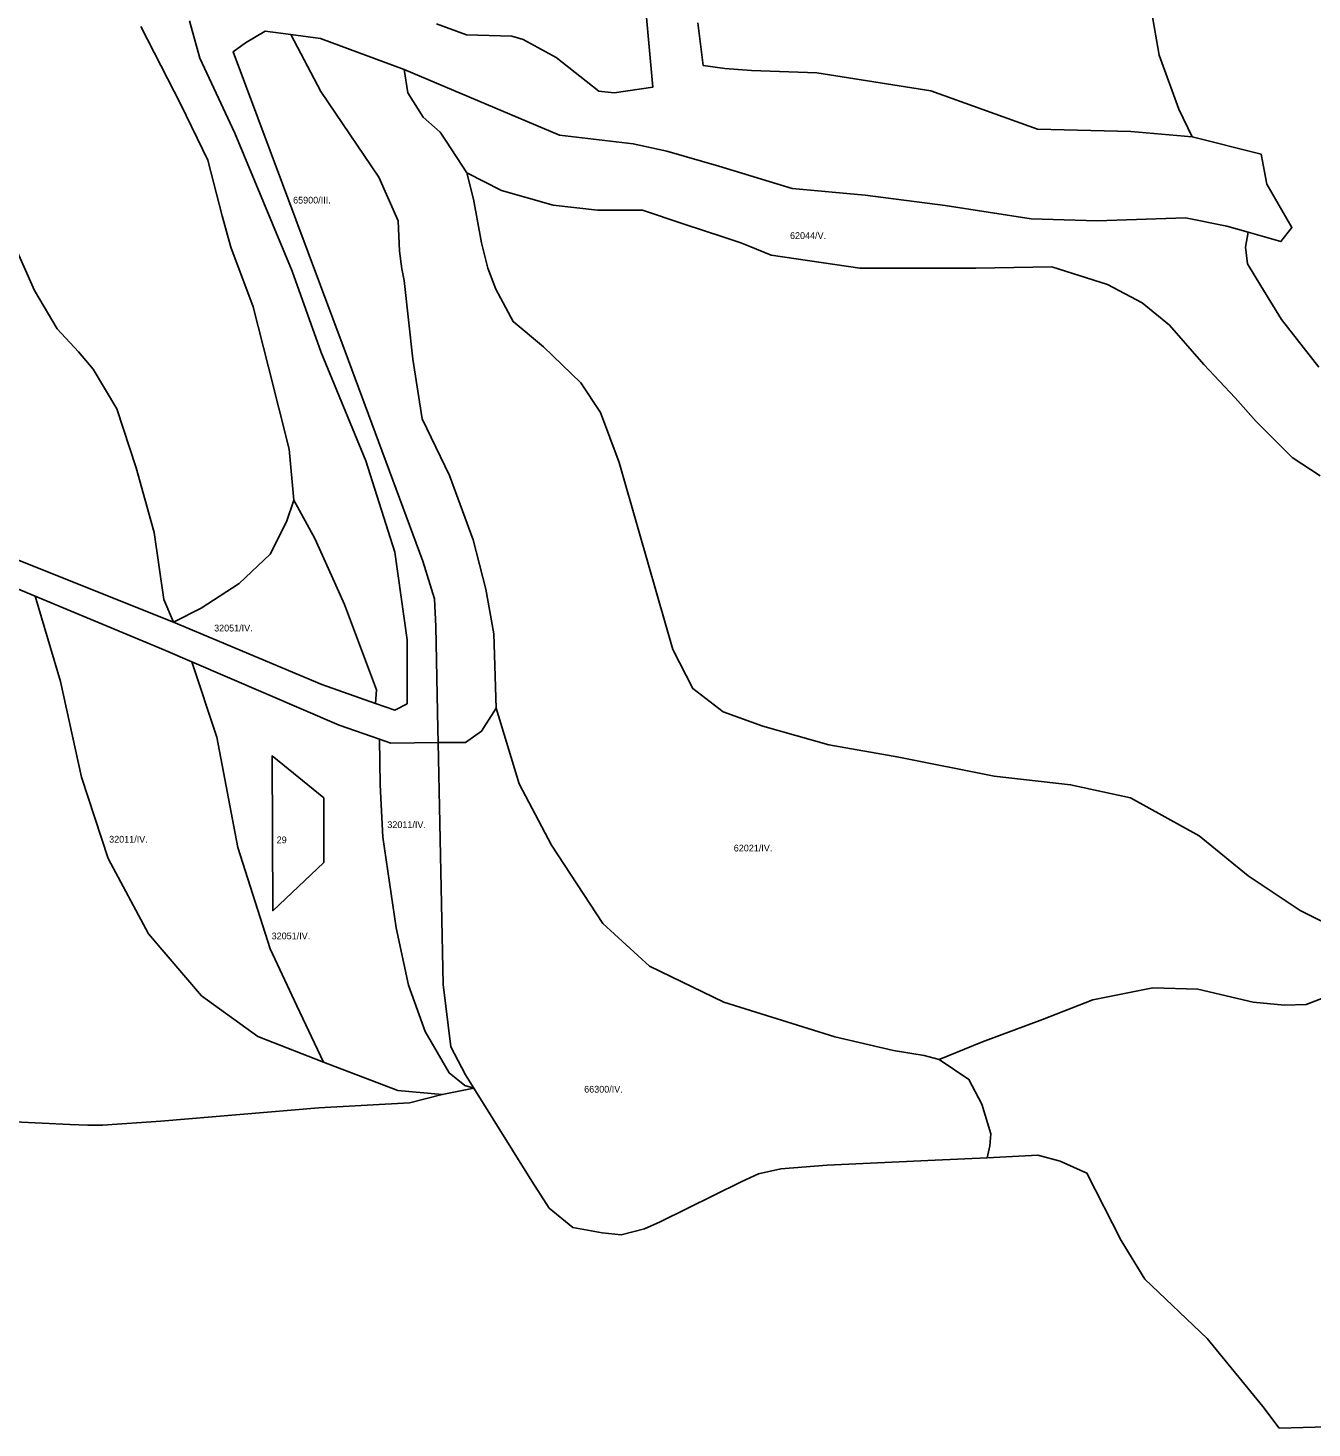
# Model space of a CAD drawing. Extents: x -521621 to -516761, y -1190184 to -1184927.
# Drawn here: x -519186 to -518423, y -1190183 to -1189352 of the extents above; entities that cross this region are included whole.
import ezdxf

# ---------------------------------------------------------------- set-up
doc = ezdxf.new("R2010")
doc.units = 0
doc.layers.add('BPEJ_s', color=7, linetype='Continuous')

msp = doc.modelspace()

# ---------------------------------------------------------------- linework, layer by layer
at = {"layer": 'BPEJ_s'}
for points in [[(-518943.04, -1189349.41), (-518925.38, -1189356.01), (-518898.42, -1189356.83), (-518891.65, -1189358.82), (-518872.1, -1189369.42), (-518846.79, -1189389.45), (-518837.55, -1189390.37), (-518814.59, -1189386.96), (-518823.53, -1189288.99)], [(-518823.53, -1189288.99), (-518814.59, -1189386.96), (-518837.55, -1189390.37), (-518846.79, -1189389.45), (-518872.1, -1189369.42), (-518891.65, -1189358.82), (-518898.42, -1189356.83), (-518925.38, -1189356.01), (-518943.04, -1189349.41)], [(-519319.63, -1189346.12), (-519285.69, -1189363.91), (-519249.6, -1189401.64), (-519219.98, -1189448.53), (-519195.73, -1189476.56), (-519181.73, -1189507.82), (-519168.26, -1189530.46), (-519155.68, -1189544.18), (-519146.92, -1189554.55), (-519132.97, -1189578.08), (-519121.41, -1189613.17), (-519110.69, -1189651.42), (-519105, -1189691.24), (-519099.22, -1189704.82), (-519192.94, -1189667.39), (-519198.41, -1189646.81), (-519206.51, -1189624.25), (-519222.13, -1189592.45), (-519250.68, -1189534.23), (-519284.62, -1189487.34), (-519329.33, -1189423.2), (-519383.19, -1189366.6), (-519421.98, -1189339.11)], [(-519192.94, -1189667.39), (-519099.22, -1189704.82), (-519011.21, -1189741.67), (-518979.39, -1189752.94), (-518967.91, -1189757.01), (-518960.64, -1189753.17), (-518960.64, -1189715.22), (-518967.91, -1189663.09), (-518985.18, -1189608.92), (-519011.61, -1189544.52), (-519028.8, -1189496.38), (-519062.9, -1189414.34), (-519083.59, -1189369.88), (-519089.69, -1189347.71)], [(-519089.69, -1189347.71), (-519083.59, -1189369.88), (-519062.9, -1189414.34), (-519028.8, -1189496.38), (-519011.61, -1189544.52), (-518985.18, -1189608.92), (-518967.91, -1189663.09), (-518960.64, -1189715.22), (-518960.64, -1189753.17), (-518967.91, -1189757.01), (-518979.39, -1189752.94), (-518978.83, -1189744.88), (-518997.79, -1189694.22), (-519005.45, -1189676.97), (-519015.41, -1189655.04), (-519027.76, -1189632.31), (-519030.55, -1189602), (-519042.91, -1189553.35), (-519052.07, -1189517.47), (-519065.22, -1189481.98), (-519070.32, -1189463.47), (-519078.92, -1189430.48), (-519094.83, -1189397.35), (-519118.62, -1189351.02)], [(-518518.65, -1189341.97), (-518513.96, -1189367.96), (-518502.42, -1189400.08), (-518494.41, -1189416.62), (-518530.95, -1189413.36), (-518586.29, -1189411.99), (-518649.58, -1189389.24), (-518717.39, -1189378.58), (-518756.02, -1189377.21), (-518771.94, -1189375.99), (-518784.77, -1189374.22), (-518788.02, -1189348.82)], [(-518494.41, -1189416.62), (-518502.42, -1189400.08), (-518513.96, -1189367.96), (-518518.65, -1189341.97)], [(-518788.02, -1189348.82), (-518784.77, -1189374.22), (-518771.94, -1189375.99), (-518756.02, -1189377.21), (-518717.39, -1189378.58), (-518649.58, -1189389.24), (-518586.29, -1189411.99), (-518530.95, -1189413.36), (-518494.41, -1189416.62), (-518453.58, -1189426.76), (-518450.16, -1189444.62), (-518435.22, -1189470.31), (-518441.74, -1189478.74), (-518461.24, -1189473.16), (-518473.92, -1189469.54), (-518498.43, -1189464.56), (-518550.92, -1189466.47), (-518590, -1189465.32), (-518641.11, -1189457.29), (-518688.61, -1189451.15), (-518731.9, -1189447.32), (-518775.54, -1189433.92), (-518806.39, -1189425.09), (-518826.4, -1189420.61), (-518870.11, -1189415.55), (-518962.42, -1189376.51), (-519011.98, -1189358.25), (-519029.54, -1189355.86), (-519044.76, -1189353.78), (-519056.53, -1189360.74), (-519063.91, -1189366.05), (-518997.44, -1189544.02), (-518951.16, -1189668.56), (-518944.27, -1189690.79), (-518943.5, -1189707.28), (-518942.29, -1189768.13), (-518942.13, -1189776.18), (-518970.3, -1189776.52), (-518976.95, -1189774.2), (-519000.83, -1189765.87), (-519088.41, -1189728.31), (-519105.42, -1189721.02), (-519181.35, -1189689.34), (-519222.81, -1189672.05)], [(-519118.62, -1189351.02), (-519094.83, -1189397.35), (-519078.92, -1189430.48), (-519070.32, -1189463.47), (-519065.22, -1189481.98), (-519052.07, -1189517.47), (-519042.91, -1189553.35), (-519030.55, -1189602), (-519027.76, -1189632.31), (-519032.17, -1189645.19), (-519041.92, -1189664.42), (-519060.33, -1189681.76), (-519082.8, -1189696.39), (-519099.22, -1189704.82), (-519105, -1189691.24), (-519110.69, -1189651.42), (-519121.41, -1189613.17), (-519132.97, -1189578.08), (-519146.92, -1189554.55), (-519155.68, -1189544.18), (-519168.26, -1189530.46), (-519181.73, -1189507.82), (-519195.73, -1189476.56)], [(-518402, -1189922.21), (-518426.87, -1189931.65), (-518439.73, -1189932.08), (-518458.17, -1189930.36), (-518491.18, -1189922.64), (-518517.77, -1189921.78), (-518553.35, -1189929.07), (-518583.37, -1189940.66), (-518618.95, -1189953.96), (-518644.71, -1189964.45), (-518653.54, -1189962.09), (-518671.79, -1189959.14), (-518706.53, -1189950.9), (-518772.48, -1189930.28), (-518816.64, -1189909.06), (-518844.31, -1189883.73), (-518874.93, -1189837.19), (-518894.09, -1189800.66), (-518907.74, -1189755.73), (-518909.06, -1189711.59), (-518913.78, -1189685.05), (-518921.36, -1189655.83), (-518935.31, -1189617.55), (-518951.65, -1189584.06), (-518957.23, -1189548.57), (-518962.41, -1189501.92), (-518963.68, -1189495.02), (-518965.19, -1189484.53), (-518965.91, -1189466.49), (-518977.46, -1189440.5), (-519011.72, -1189389.61), (-519029.54, -1189355.86), (-519011.98, -1189358.25), (-518962.42, -1189376.51), (-518960.14, -1189390.33), (-518951.12, -1189404.77), (-518941.03, -1189413.79), (-518937.42, -1189419.21), (-518925.16, -1189437.98), (-518921.19, -1189453.5), (-518916.5, -1189479.48), (-518912.66, -1189494.45), (-518907.93, -1189506.92), (-518897.65, -1189526.22), (-518879.64, -1189541.24), (-518857.34, -1189562.69), (-518845.77, -1189580.28), (-518834.62, -1189609.88), (-518823.04, -1189650.64), (-518812.32, -1189687.96), (-518802.89, -1189721), (-518790.88, -1189744.17), (-518772.88, -1189757.89), (-518749.29, -1189766.48), (-518710.28, -1189777.63), (-518668.69, -1189784.92), (-518612.09, -1189796.08), (-518566.64, -1189801.23), (-518531.06, -1189808.95), (-518490.33, -1189831.69), (-518461.17, -1189855.28), (-518430.3, -1189875.88), (-518397.71, -1189892.18)], [(-518418.55, -1189617.83), (-518435.07, -1189606.94), (-518456.42, -1189585.57), (-518468.91, -1189571.46), (-518487.45, -1189551.71), (-518507.99, -1189528.33), (-518524.11, -1189515.02), (-518544.66, -1189504.14), (-518577.7, -1189493.65), (-518622.82, -1189494.46), (-518691.72, -1189494.46), (-518744.5, -1189486.8), (-518757.39, -1189481.56), (-518762.48, -1189479.48), (-518771.86, -1189476.23), (-518796.75, -1189468.29), (-518820.91, -1189459.99), (-518847.61, -1189459.99), (-518873.94, -1189457.1), (-518904.6, -1189448.44), (-518925.16, -1189437.98), (-518937.42, -1189419.21), (-518941.03, -1189413.79), (-518951.12, -1189404.77), (-518960.14, -1189390.33), (-518962.42, -1189376.51), (-518870.11, -1189415.55), (-518826.4, -1189420.61), (-518806.39, -1189425.09), (-518775.54, -1189433.92), (-518731.9, -1189447.32), (-518688.61, -1189451.15), (-518641.11, -1189457.29), (-518590, -1189465.32), (-518550.92, -1189466.47), (-518498.43, -1189464.56), (-518473.92, -1189469.54), (-518461.24, -1189473.16), (-518462.87, -1189481.96), (-518461.66, -1189492.04), (-518453.6, -1189504.94), (-518441.51, -1189525.1), (-518419.35, -1189553.32)], [(-518461.24, -1189473.16), (-518441.74, -1189478.74), (-518435.22, -1189470.31), (-518450.16, -1189444.62), (-518453.58, -1189426.76), (-518494.41, -1189416.62)], [(-518397.71, -1189892.18), (-518430.3, -1189875.88), (-518461.17, -1189855.28), (-518490.33, -1189831.69), (-518531.06, -1189808.95), (-518566.64, -1189801.23), (-518612.09, -1189796.08), (-518668.69, -1189784.92), (-518710.28, -1189777.63), (-518749.29, -1189766.48), (-518772.88, -1189757.89), (-518790.88, -1189744.17), (-518802.89, -1189721), (-518812.32, -1189687.96), (-518823.04, -1189650.64), (-518834.62, -1189609.88), (-518845.77, -1189580.28), (-518857.34, -1189562.69), (-518879.64, -1189541.24), (-518897.65, -1189526.22), (-518907.93, -1189506.92), (-518912.66, -1189494.45), (-518916.5, -1189479.48), (-518921.19, -1189453.5), (-518925.16, -1189437.98)], [(-518925.16, -1189437.98), (-518904.6, -1189448.44), (-518873.94, -1189457.1), (-518847.61, -1189459.99), (-518820.91, -1189459.99), (-518796.75, -1189468.29), (-518771.86, -1189476.23), (-518762.48, -1189479.48), (-518757.39, -1189481.56), (-518744.5, -1189486.8), (-518691.72, -1189494.46), (-518622.82, -1189494.46), (-518577.7, -1189493.65), (-518544.66, -1189504.14), (-518524.11, -1189515.02), (-518507.99, -1189528.33), (-518487.45, -1189551.71), (-518468.91, -1189571.46), (-518456.42, -1189585.57), (-518435.07, -1189606.94), (-518418.55, -1189617.83)], [(-518419.35, -1189553.32), (-518441.51, -1189525.1), (-518453.6, -1189504.94), (-518461.66, -1189492.04), (-518462.87, -1189481.96), (-518461.24, -1189473.16)], [(-518414.24, -1190182.61), (-518442.72, -1190183.21), (-518452.6, -1190170.53), (-518485.54, -1190130), (-518522.62, -1190094.81), (-518536.63, -1190071.93), (-518556.95, -1190031.84), (-518572.82, -1190024.72), (-518586.03, -1190021.3), (-518616.23, -1190022.72), (-518614.68, -1190015.7), (-518614.09, -1190008.63), (-518619.39, -1189990.96), (-518627.04, -1189976.23), (-518644.71, -1189964.45), (-518618.95, -1189953.96), (-518583.37, -1189940.66), (-518553.35, -1189929.07), (-518517.77, -1189921.78), (-518491.18, -1189922.64), (-518458.17, -1189930.36), (-518439.73, -1189932.08), (-518426.87, -1189931.65), (-518402, -1189922.21)]]:
    msp.add_lwpolyline(points, dxfattribs=at)
for points in [[(-519029.54, -1189355.86), (-519011.72, -1189389.61), (-518977.46, -1189440.5), (-518965.91, -1189466.49), (-518965.19, -1189484.53), (-518963.68, -1189495.02), (-518962.41, -1189501.92), (-518957.23, -1189548.57), (-518951.65, -1189584.06), (-518935.31, -1189617.55), (-518921.36, -1189655.83), (-518913.78, -1189685.05), (-518909.06, -1189711.59), (-518907.74, -1189755.73), (-518916.41, -1189769.39), (-518925.86, -1189776.22), (-518942.13, -1189776.18), (-518942.29, -1189768.13), (-518943.5, -1189707.28), (-518944.27, -1189690.79), (-518951.16, -1189668.56), (-518997.44, -1189544.02), (-519063.91, -1189366.05), (-519056.53, -1189360.74), (-519044.76, -1189353.78)], [(-519208.1, -1190001.4), (-519253.62, -1189849.21), (-519288, -1189744.93), (-519311.71, -1189668.82), (-519328.03, -1189629.94), (-519222.81, -1189672.05), (-519181.35, -1189689.34), (-519166.46, -1189740.01), (-519153.87, -1189796.77), (-519138.14, -1189844.98), (-519114.04, -1189889.74), (-519082.58, -1189926.64), (-519049.15, -1189950.75), (-519010.3, -1189966), (-518966.06, -1189982.72), (-518939.67, -1189985.22), (-518959.14, -1189990.09), (-519013.06, -1189993.13), (-519106.78, -1190001.04), (-519141.44, -1190003.47), (-519150.16, -1190003.47), (-519160.74, -1190002.98), (-519193.76, -1190001.45)], [(-519099.22, -1189704.82), (-519082.8, -1189696.39), (-519060.33, -1189681.76), (-519041.92, -1189664.42), (-519032.17, -1189645.19), (-519027.76, -1189632.31), (-519015.41, -1189655.04), (-519005.45, -1189676.97), (-518997.79, -1189694.22), (-518978.83, -1189744.88), (-518979.39, -1189752.94), (-519011.21, -1189741.67)], [(-519181.35, -1189689.34), (-519105.42, -1189721.02), (-519088.41, -1189728.31), (-519073.59, -1189773.06), (-519061.15, -1189838.48), (-519041.95, -1189898.79), (-519026.05, -1189932.59), (-519010.3, -1189966), (-519049.15, -1189950.75), (-519082.58, -1189926.64), (-519114.04, -1189889.74), (-519138.14, -1189844.98), (-519153.87, -1189796.77), (-519166.46, -1189740.01)], [(-519088.41, -1189728.31), (-519000.83, -1189765.87), (-518976.95, -1189774.2), (-518976.67, -1189801.23), (-518974.96, -1189832.45), (-518967.04, -1189886.3), (-518959.66, -1189920.25), (-518949.83, -1189947.8), (-518935.57, -1189972.39), (-518926.23, -1189979.77), (-518920.92, -1189981.41), (-518939.67, -1189985.22), (-518966.06, -1189982.72), (-519010.3, -1189966), (-519026.05, -1189932.59), (-519041.95, -1189898.79), (-519061.15, -1189838.48), (-519073.59, -1189773.06)], [(-518942.13, -1189776.18), (-518925.86, -1189776.22), (-518916.41, -1189769.39), (-518907.74, -1189755.73), (-518894.09, -1189800.66), (-518874.93, -1189837.19), (-518844.31, -1189883.73), (-518816.64, -1189909.06), (-518772.48, -1189930.28), (-518706.53, -1189950.9), (-518671.79, -1189959.14), (-518653.54, -1189962.09), (-518644.71, -1189964.45), (-518627.04, -1189976.23), (-518619.39, -1189990.96), (-518614.09, -1190008.63), (-518614.68, -1190015.7), (-518616.23, -1190022.72), (-518647.01, -1190024.17), (-518711.08, -1190027.21), (-518738.66, -1190029.23), (-518752.04, -1190032.27), (-518762.24, -1190037.03), (-518810.3, -1190060.77), (-518819.62, -1190065.03), (-518833.41, -1190068.48), (-518844.76, -1190067.27), (-518862.21, -1190064.22), (-518876.19, -1190052.66), (-518886.45, -1190036.6), (-518920.92, -1189981.41), (-518925.93, -1189973.44), (-518934.52, -1189956.82), (-518939.26, -1189919.86)], [(-518976.95, -1189774.2), (-518970.3, -1189776.52), (-518942.13, -1189776.18), (-518939.26, -1189919.86), (-518934.52, -1189956.82), (-518925.93, -1189973.44), (-518920.92, -1189981.41), (-518926.23, -1189979.77), (-518935.57, -1189972.39), (-518949.83, -1189947.8), (-518959.66, -1189920.25), (-518967.04, -1189886.3), (-518974.96, -1189832.45), (-518976.67, -1189801.23)], [(-519010.1, -1189809.02), (-519010.1, -1189847.36), (-519040.36, -1189876.11), (-519040.75, -1189784.11)], [(-519010.1, -1189809.02), (-519010.1, -1189847.36), (-519040.36, -1189876.11), (-519040.75, -1189784.11)]]:
    msp.add_lwpolyline(points, close=True, dxfattribs=at)

# ---------------------------------------------------------------- texts
for s, p in [('65900/III.', (-519028.25, -1189456.14)), ('62044/V.', (-518733.23, -1189477.16)), ('32051/IV.', (-519075.17, -1189710.25)), ('32011/IV.', (-518972.32, -1189826.98)), ('32011/IV.', (-519137.48, -1189835.61)), ('29', (-519038.01, -1189835.99)), ('62021/IV.', (-518766.63, -1189840.87)), ('32051/IV.', (-519041.01, -1189893.04)), ('66300/IV.', (-518855.45, -1189984.05))]:
    msp.add_text(s, height=4, dxfattribs=at).set_placement(p)

doc.saveas('drawing.dxf')
